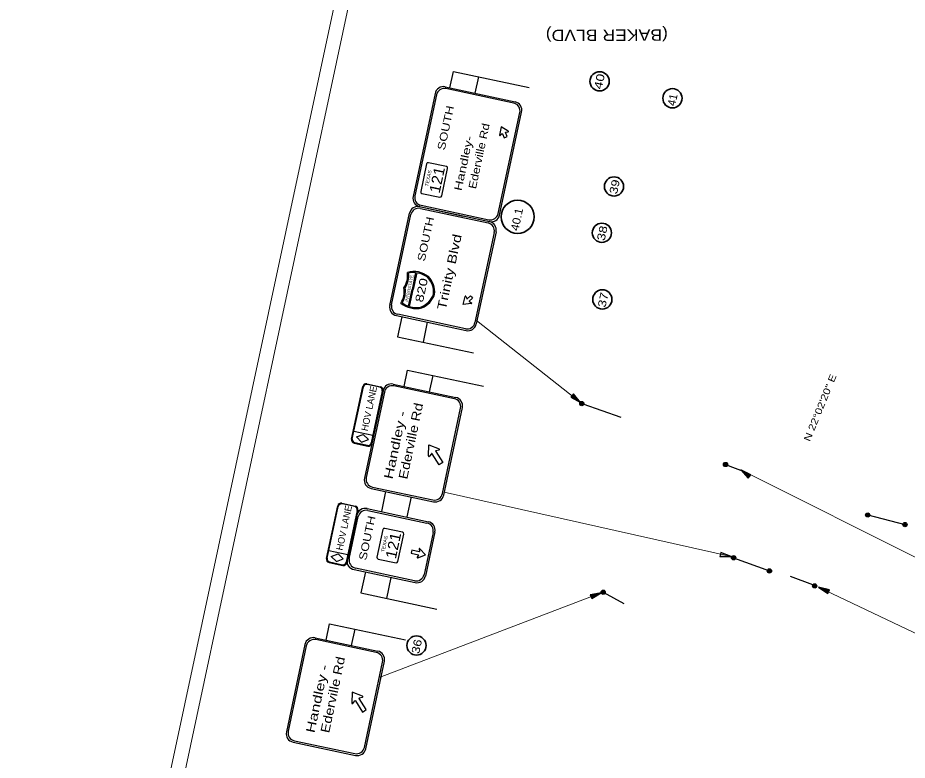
# Model space of a CAD drawing. Extents: x 2363411 to 2369702, y 6977197 to 6988655.
# Drawn here: x 2363411 to 2364967, y 6979218 to 6980518 of the extents above; entities that cross this region are included whole.
import ezdxf
from ezdxf.enums import TextEntityAlignment as Align

# ---------------------------------------------------------------- set-up
doc = ezdxf.new("R2010")
doc.units = 0
doc.header["$LTSCALE"] = 5.6
for name, color, linetype, lineweight in [('1', 7, 'Continuous', 25), ('10', 7, 'Continuous', 13), ('13', 7, 'Continuous', 13), ('17', 7, 'Continuous', 35), ('48', 7, 'Continuous', 25)]:
    doc.layers.add(name, color=color, linetype=linetype, lineweight=lineweight)
doc.layers.add('28', color=7, linetype='Continuous')

msp = doc.modelspace()

# ---------------------------------------------------------------- hatches: boundary and pattern name
at = {"layer": '1'}
for points in [[(2364395.849, 6979844.391), (2364383.344, 6979859.395), (2364378.757, 6979853.851)], [(2364400.643, 6979844.979, 1), (2364395.253, 6979839.817, 1)], [(2364652.119, 6979738.397, 1), (2364646.635, 6979733.335, 1)], [(2364675.941, 6979726.259), (2364689.19, 6979711.901), (2364693.5, 6979717.691)], [(2364900.421, 6979650.311, 1), (2364895.482, 6979644.716, 1)], [(2364965.668, 6979633.538, 1), (2364960.729, 6979627.943, 1)], [(2364659.135, 6979575), (2364640.906, 6979582.012), (2364639.602, 6979574.934)], [(2364665.911, 6979575.535, 1), (2364660.969, 6979569.942, 1)], [(2364728.487, 6979552.379, 1), (2364723.545, 6979546.786, 1)], [(2364438.384, 6979514.445, 1), (2364432.244, 6979510.203, 1)], [(2364807.983, 6979525.907, 1), (2364802.499, 6979520.845, 1)], [(2364811.897, 6979521.098), (2364828.08, 6979510.162), (2364830.948, 6979516.769)], [(2364432.027, 6979511.264), (2364412.779, 6979507.95), (2364415.284, 6979501.204)]]:
    msp.add_hatch(color=256, dxfattribs=at).paths.add_polyline_path(points)

# ---------------------------------------------------------------- linework, layer by layer
for p, q in [((2364167.135, 6980395.064), (2364173.274, 6980423.795)), ((2364173.274, 6980423.795), (2364305.856, 6980395.467)), ((2364211.638, 6980385.554), (2364217.777, 6980414.287)), ((2364159.115, 6980396.778), (2364281.159, 6980370.698)), ((2364281.102, 6980367.815), (2364160.369, 6980393.619)), ((2364141.265, 6980385.212), (2364102.765, 6980205.026)), ((2364143.627, 6980382.783), (2364105.906, 6980206.28)), ((2364251.811, 6980175.104), (2364289.567, 6980351.79)), ((2364254.104, 6980172.382), (2364292.597, 6980352.561)), ((2364255.297, 6980311.725), (2364258.277, 6980314.629)), ((2364264.669, 6980317.552), (2364268.795, 6980317.874)), ((2364269.112, 6980319.29), (2364269.086, 6980319.295)), ((2364161.015, 6980257.291), (2364129.782, 6980263.971)), ((2364126.447, 6980261.812), (2364116.153, 6980213.654)), ((2364152.886, 6980205.805), (2364163.181, 6980253.956)), ((2364118.319, 6980210.319), (2364149.551, 6980203.639)), ((2364114.33, 6980187.162), (2364236.725, 6980161.005)), ((2364114.33, 6980187.162), (2364191.247, 6980170.724)), ((2364116.766, 6980189.531), (2364235.118, 6980164.239)), ((2364062.029, 6980014.151), (2364096.539, 6980175.632)), ((2364065.17, 6980015.396), (2364098.9, 6980173.209)), ((2364115.583, 6980184.027), (2364233.929, 6980158.736)), ((2364244.748, 6980142.053), (2364211.027, 6979984.233)), ((2364247.883, 6980143.299), (2364213.379, 6979981.811)), ((2364107.307, 6980071.579), (2364101.041, 6980042.241)), ((2364109.199, 6980071.369), (2364102.89, 6980041.849)), ((2364094.775, 6980012.905), (2364101.041, 6980042.241)), ((2364096.583, 6980012.305), (2364102.89, 6980041.849)), ((2364195.117, 6980030.073), (2364196.649, 6980026.204)), ((2364197.436, 6980026.006), (2364197.448, 6980026.015)), ((2364201.289, 6980020.924), (2364204.923, 6980018.944)), ((2364194.344, 6979973.413), (2364075.983, 6979998.705)), ((2364073.575, 6979996.353), (2364195.589, 6979970.272)), ((2364083.219, 6979994.292), (2364075.789, 6979959.519)), ((2364127.721, 6979984.779), (2364120.293, 6979950.009)), ((2364075.789, 6979959.519), (2364208.371, 6979931.191)), ((2364087.14, 6979872.511), (2364093.279, 6979901.242)), ((2364093.279, 6979901.242), (2364225.861, 6979872.914)), ((2364131.643, 6979863.001), (2364137.782, 6979891.734)), ((2364068.045, 6979876.561), (2364177.43, 6979853.362)), ((2364175.005, 6979850.975), (2364069.311, 6979873.399)), ((2364050.211, 6979864.973), (2364017.718, 6979711.873)), ((2364052.569, 6979862.531), (2364020.85, 6979713.13)), ((2364154.184, 6979684.842), (2364185.895, 6979834.249)), ((2364156.54, 6979682.423), (2364189.035, 6979835.5)), ((2364399.628, 6979841.745), (2364466.091, 6979818.436)), ((2364129.725, 6979750.995), (2364130.48, 6979770.154)), ((2364130.48, 6979770.154), (2364148.254, 6979762.998)), ((2364134.884, 6979754.713), (2364131.548, 6979750.291)), ((2364148.547, 6979735.278), (2364136.006, 6979754.674)), ((2364148.151, 6979761.06), (2364142.742, 6979759.8)), ((2364649.381, 6979735.877), (2364688.003, 6979721.52)), ((2364029.292, 6979694.024), (2364138.684, 6979670.818)), ((2364031.74, 6979696.404), (2364137.434, 6979673.981)), ((2364054.763, 6979688.621), (2364047.333, 6979653.848)), ((2364099.265, 6979679.108), (2364091.837, 6979644.338)), ((2363989.737, 6979576.334), (2364006.381, 6979656.061)), ((2364022.274, 6979658.714), (2364129.853, 6979635.724)), ((2364023.528, 6979655.581), (2364127.058, 6979633.455)), ((2363991.052, 6979570.875), (2364006.844, 6979644.762)), ((2364897.949, 6979647.508), (2364963.203, 6979630.739)), ((2364049.852, 6979621.948), (2364039.558, 6979573.79)), ((2364084.42, 6979617.427), (2364053.187, 6979624.107)), ((2364076.291, 6979565.941), (2364086.586, 6979614.092)), ((2364137.876, 6979616.771), (2364122.157, 6979543.218)), ((2364141.011, 6979618.017), (2364124.448, 6979540.493)), ((2364113.435, 6979583.245), (2364113.424, 6979583.252)), ((2364113.528, 6979587.919), (2364114.043, 6979583.813)), ((2364041.724, 6979570.455), (2364072.956, 6979563.775)), ((2364112.468, 6979576.963), (2364110.222, 6979573.46)), ((2364663.442, 6979572.748), (2364726.016, 6979549.582)), ((2363999.523, 6979552.172), (2364106.722, 6979529.256)), ((2364105.476, 6979532.398), (2364001.93, 6979554.524)), ((2364019.498, 6979547.902), (2364011.642, 6979511.135)), ((2364064, 6979538.389), (2364056.146, 6979501.625)), ((2364762.642, 6979540.186), (2364801.264, 6979525.829)), ((2364011.642, 6979511.135), (2364144.224, 6979482.807)), ((2364435.318, 6979512.333), (2364471.648, 6979492.652)), ((2363950.653, 6979428.484), (2363956.792, 6979457.215)), ((2363956.792, 6979457.215), (2364089.374, 6979428.887)), ((2363995.156, 6979418.974), (2364001.295, 6979447.707)), ((2363931.558, 6979432.534), (2364040.943, 6979409.335)), ((2364038.518, 6979406.948), (2363932.824, 6979429.372)), ((2363913.724, 6979420.946), (2363881.231, 6979267.846)), ((2363916.082, 6979418.504), (2363884.363, 6979269.103)), ((2364020.053, 6979238.396), (2364052.548, 6979391.473)), ((2364017.697, 6979240.815), (2364049.408, 6979390.222)), ((2363997.515, 6979317.748), (2364000.851, 6979322.17)), ((2364001.973, 6979322.131), (2364014.514, 6979302.735)), ((2364020.861, 6979306.859), (2364008.311, 6979326.233)), ((2364008.709, 6979327.257), (2364014.118, 6979328.517)), ((2363895.253, 6979252.377), (2364000.947, 6979229.954)), ((2363892.805, 6979249.997), (2364002.197, 6979226.791))]:
    msp.add_line(p, q, dxfattribs=at)
at = {"layer": '1', "lineweight": 13}
for p, q in [((2364395.849, 6979844.391), (2364213.976, 6979987.64)), ((2364675.941, 6979726.259), (2365587.007, 6979269.736)), ((2364659.135, 6979575), (2364157.357, 6979687.495)), ((2364811.897, 6979521.098), (2365602.925, 6979144.273)), ((2364432.009, 6979511.012), (2364045.483, 6979363.861))]:
    msp.add_line(p, q, dxfattribs=at)
at = {"layer": '1'}
for points in [[(2364269.086, 6980319.295), (2364256.691, 6980326.558), (2364254.03, 6980312.435)], [(2364259.083, 6980314.476), (2364262.306, 6980307.386), (2364264.883, 6980308.563), (2364267.459, 6980309.748), (2364264.238, 6980316.823)], [(2364204.607, 6980017.529), (2364190.327, 6980015.966), (2364193.671, 6980029.943)], [(2364197.448, 6980026.015), (2364203.287, 6980031.169), (2364205.159, 6980029.041), (2364207.025, 6980026.907), (2364201.193, 6980021.767)], [(2364142.344, 6979758.776), (2364154.894, 6979739.402), (2364151.725, 6979737.342), (2364148.556, 6979735.284)], [(2364113.424, 6979583.252), (2364100.874, 6979586.105), (2364100.235, 6979583.341), (2364099.6, 6979580.58), (2364112.156, 6979577.721)], [(2364111.172, 6979572.36), (2364124.471, 6979577.813), (2364114.863, 6979588.489)], [(2364014.221, 6979330.455), (2363996.447, 6979337.611), (2363995.692, 6979318.452)], [(2364014.523, 6979302.741), (2364017.692, 6979304.799), (2364020.861, 6979306.859)]]:
    msp.add_lwpolyline(points, dxfattribs=at)
for points in [[(2364395.849, 6979844.391), (2364383.344, 6979859.395), (2364378.757, 6979853.851)], [(2364675.941, 6979726.259), (2364689.19, 6979711.901), (2364693.5, 6979717.691)], [(2364659.135, 6979575), (2364640.906, 6979582.012), (2364639.602, 6979574.934)], [(2364811.897, 6979521.098), (2364828.08, 6979510.162), (2364830.948, 6979516.769)], [(2364432.027, 6979511.264), (2364412.779, 6979507.95), (2364415.284, 6979501.204)]]:
    msp.add_lwpolyline(points, close=True, dxfattribs=at)
for centre in [(2364397.948, 6979842.398), (2364649.377, 6979735.866), (2364897.952, 6979647.513), (2364963.199, 6979630.741), (2364663.44, 6979572.739), (2364726.016, 6979549.582), (2364435.314, 6979512.324), (2364805.241, 6979523.376)]:
    msp.add_circle(centre, 3.732, dxfattribs=at)
for centre, radius, start, end in [((2364155.977, 6980382.065), 15.049, 77.93925, 169.35675), ((2364157.424, 6980379.833), 14.108, 77.93925, 167.93925), ((2364275.77, 6980354.738), 14.108, 347.93925, 68.3439), ((2364277.948, 6980356.005), 15.049, 346.76968, 76.63979), ((2364254.773, 6980312.274), 0.759, 169.23551, 314.61665), ((2364258.615, 6980314.28), 0.506, 24.49701, 134.48012), ((2364264.696, 6980317.051), 0.506, 94.51391, 204.49701), ((2364268.729, 6980318.634), 0.759, 274.37738, 59.75852), ((2364129.197, 6980261.219), 2.813, 77.93906, 167.93906), ((2364160.425, 6980254.547), 2.813, 347.93906, 77.93906), ((2364117.48, 6980201.884), 15.049, 167.93925, 257.93925), ((2364119.713, 6980203.331), 14.108, 167.93925, 257.93925), ((2364118.909, 6980213.066), 2.813, 167.93906, 257.93906), ((2364150.136, 6980206.394), 2.813, 257.93906, 347.93906), ((2364111.206, 6980172.499), 15.001, 77.94013, 167.94013), ((2364112.648, 6980170.273), 14.063, 77.94013, 167.94013), ((2364238.015, 6980178.052), 14.108, 257.93925, 347.93925), ((2364239.454, 6980175.826), 15.049, 257.93925, 346.76968), ((2364230.995, 6980144.989), 14.063, 347.94013, 77.94013), ((2364233.221, 6980146.431), 15.001, 347.94013, 77.94013), ((2364057.337, 6980065.842), 35.984, 325.11963, 9.96995), ((2364057.337, 6980065.842), 37.874, 326.31755, 7.31439), ((2364103.993, 6980031.645), 41.954, 51.80243, 105.50481), ((2364103.993, 6980031.645), 40.064, 85.24888, 103.11363), ((2364103.993, 6980031.645), 40.064, 52.01897, 82.53095), ((2364100.001, 6980037.044), 38.808, 355.77729, 42.42367), ((2364100.001, 6980037.044), 40.698, 355.41114, 42.64704), ((2364051.505, 6980038.547), 35.984, 325.90855, 10.75886), ((2364051.505, 6980038.547), 37.874, 328.56411, 9.56095), ((2364102.213, 6980047.395), 38.808, 293.45483, 340.10121), ((2364102.213, 6980047.395), 40.698, 293.23145, 340.46735), ((2364194.415, 6980029.786), 0.759, 21.26148, 166.64261), ((2364076.7, 6980011.015), 15.001, 167.94013, 257.94013), ((2364078.925, 6980012.457), 14.063, 167.94013, 257.94013), ((2364108.062, 6980050.691), 41.954, 230.37369, 284.07606), ((2364108.062, 6980050.691), 40.064, 232.76486, 250.62962), ((2364197.101, 6980026.386), 0.506, 201.398, 311.38111), ((2364201.519, 6980021.372), 0.506, 131.38111, 241.36421), ((2364204.553, 6980018.279), 0.759, 276.1196, 61.50074), ((2364108.062, 6980050.691), 40.064, 253.34754, 283.85953), ((2364197.273, 6979987.172), 14.063, 257.94013, 347.94013), ((2364198.715, 6979984.947), 15.001, 257.94013, 347.94013), ((2364064.927, 6979861.846), 15.049, 78.01448, 168.01448), ((2364066.376, 6979859.615), 14.108, 78.01448, 168.01447), ((2364172.091, 6979837.19), 14.108, 348.01448, 78.01448), ((2364174.322, 6979838.639), 15.049, 348.01447, 78.01447), ((2364130.74, 6979750.922), 1.012, 177.67774, 323.05888), ((2364135.414, 6979754.318), 0.675, 32.93925, 142.92235), ((2364142.892, 6979759.163), 0.675, 102.95614, 212.93925), ((2364147.902, 6979762.041), 1.012, 282.81961, 68.20075), ((2364032.426, 6979708.751), 15.049, 168.01448, 258.01448), ((2364034.657, 6979710.201), 14.108, 168.01447, 258.01447), ((2364140.371, 6979687.776), 14.108, 258.01447, 348.01447), ((2364141.821, 6979685.545), 15.049, 258.01447, 348.01447), ((2364019.149, 6979644.05), 15.001, 77.94013, 167.94013), ((2364020.591, 6979641.825), 14.063, 77.94013, 167.94013), ((2364124.122, 6979619.706), 14.063, 347.94013, 77.94013), ((2364126.348, 6979621.148), 15.001, 347.94013, 77.94013), ((2364052.602, 6979621.355), 2.813, 77.93906, 167.93906), ((2364083.829, 6979614.682), 2.813, 347.93906, 77.93906), ((2364112.058, 6979577.224), 0.506, 327.13184, 77.11494), ((2364113.548, 6979583.738), 0.506, 257.11494, 7.09805), ((2364114.287, 6979588.008), 0.759, 41.85344, 187.23458), ((2364004.873, 6979568.274), 14.063, 167.94013, 257.94013), ((2364042.313, 6979573.202), 2.813, 167.93906, 257.93906), ((2364073.541, 6979566.529), 2.813, 257.93906, 347.93906), ((2364110.867, 6979573.058), 0.759, 146.99531, 292.37645), ((2364108.404, 6979546.155), 14.063, 257.94013, 347.94013), ((2364109.846, 6979543.93), 15.001, 257.94013, 347.94013), ((2363928.44, 6979417.819), 15.049, 78.01448, 168.01448), ((2363929.889, 6979415.588), 14.108, 78.01448, 168.01447), ((2364035.604, 6979393.163), 14.108, 348.01448, 78.01448), ((2364037.834, 6979394.613), 15.049, 348.01447, 78.01447), ((2364013.868, 6979329.498), 1.012, 282.81961, 68.20075), ((2363996.707, 6979318.379), 1.012, 177.67774, 323.05888), ((2364001.38, 6979321.776), 0.675, 32.93925, 142.92235), ((2364008.858, 6979326.621), 0.675, 102.95614, 212.93925), ((2363895.939, 6979264.725), 15.049, 168.01448, 258.01448), ((2363898.17, 6979266.174), 14.108, 168.01447, 258.01447), ((2364003.884, 6979243.749), 14.108, 258.01447, 348.01447), ((2364005.334, 6979241.518), 15.049, 258.01447, 348.01447)]:
    msp.add_arc(centre, radius, start, end, dxfattribs=at)
msp.add_ellipse((2364002.685, 6979564.764), major_axis=(-15.18, 0), ratio=0.848877, start_param=6.07270093, end_param=7.64349725, dxfattribs=at)
at = {"layer": '10'}
for p, q in [((2363411.416, 6977949.748), (2365605.51, 6988218.434)), ((2363435.864, 6977944.524), (2365629.958, 6988213.21))]:
    msp.add_line(p, q, dxfattribs=at)
at = {"layer": '17'}
for centre, radius in [((2364429.066, 6980406.364), 16.828), ((2364556.437, 6980376.782), 16.828), ((2364454.242, 6980222.417), 16.828), ((2364285.71, 6980169.356), 29.053), ((2364433.042, 6980141.365), 16.828), ((2364433.849, 6980024.797), 16.828), ((2364108.769, 6979419.141), 16.828)]:
    msp.add_circle(centre, radius, dxfattribs=at)
at = {"layer": '48'}
for p, q in [((2364021.941, 6979877.055), (2364045.667, 6979871.986)), ((2364044.714, 6979871.06), (2364022.43, 6979875.821)), ((2363995.22, 6979780.272), (2364014.933, 6979872.515)), ((2363996.452, 6979780.764), (2364015.85, 6979871.561)), ((2364048.972, 6979864.482), (2364029.575, 6979773.685)), ((2363999.377, 6979794.453), (2364032.5, 6979787.375)), ((2364003.599, 6979784.054), (2364015.527, 6979788.554)), ((2364012.646, 6979775.071), (2364003.599, 6979784.054)), ((2364024.574, 6979779.572), (2364015.527, 6979788.554)), ((2363999.763, 6979773.258), (2364023.619, 6979768.16)), ((2364000.718, 6979774.187), (2364023.001, 6979769.424)), ((2364012.646, 6979775.071), (2364024.574, 6979779.572)), ((2363951.386, 6979571.358), (2363971.099, 6979663.601)), ((2363952.618, 6979571.85), (2363972.016, 6979662.647)), ((2363978.108, 6979668.142), (2364001.834, 6979663.072)), ((2364000.88, 6979662.146), (2363978.597, 6979666.907)), ((2364005.138, 6979655.568), (2363985.741, 6979564.771)), ((2364006.377, 6979656.062), (2363986.672, 6979563.817)), ((2363955.543, 6979585.539), (2363988.666, 6979578.461)), ((2363959.765, 6979575.14), (2363971.693, 6979579.64)), ((2363980.74, 6979570.658), (2363971.693, 6979579.64)), ((2363955.93, 6979564.344), (2363979.786, 6979559.246)), ((2363956.884, 6979565.273), (2363979.168, 6979560.51)), ((2363968.812, 6979566.157), (2363959.765, 6979575.14)), ((2363968.812, 6979566.157), (2363980.74, 6979570.658))]:
    msp.add_line(p, q, dxfattribs=at)
for centre, radius, start, end in [((2364020.709, 6979871.278), 5.909, 77.93633, 167.93633), ((2364021.277, 6979870.402), 5.54, 77.93633, 167.93633), ((2364043.555, 6979865.638), 5.54, 347.93633, 77.93633), ((2364044.432, 6979866.208), 5.909, 347.93633, 77.93633), ((2364000.998, 6979779.036), 5.909, 167.93575, 257.93575), ((2364001.875, 6979779.604), 5.54, 167.93575, 257.93575), ((2364024.159, 6979774.841), 5.54, 257.93575, 347.93575), ((2364024.728, 6979773.966), 5.909, 257.93575, 347.93575), ((2363976.876, 6979662.365), 5.909, 77.93633, 167.93633), ((2363977.444, 6979661.488), 5.54, 77.93633, 167.93633), ((2363999.722, 6979656.724), 5.54, 347.93633, 77.93633), ((2364000.599, 6979657.292), 5.909, 347.93633, 77.93633), ((2363957.164, 6979570.122), 5.909, 167.93575, 257.93575), ((2363958.041, 6979570.69), 5.54, 167.93575, 257.93575), ((2363980.326, 6979565.927), 5.54, 257.93575, 347.93575), ((2363980.894, 6979565.051), 5.909, 257.93575, 347.93575)]:
    msp.add_arc(centre, radius, start, end, dxfattribs=at)

# ---------------------------------------------------------------- texts
at = {"layer": '1'}
for s, height, rotation, width, p in [('SOUTH', 13.5, 77.94, 1.25, (2364166.371, 6980323.606)), ('Ederville Rd', 13.5, 77.94, 1.2, (2364224.84, 6980274.247)), ('Handley-', 13.5, 77.94, 1.35, (2364197.716, 6980261.638)), ('SOUTH', 13.5, 77.94, 1.25, (2364131.406, 6980129.121)), ('Trinity Blvd', 15.68, 77.939, 1.3, (2364173.999, 6980071.324)), ('Ederville Rd', 15.68, 78.014, 1.2, (2364106.531, 6979775.41)), ('Handley -', 15.68, 78.014, 1.35, (2364079.321, 6979768.47)), ('SOUTH', 13.5, 77.94, 1.25, (2364029.039, 6979605.905)), ('Ederville Rd', 15.68, 78.014, 1.2, (2363970.044, 6979331.384)), ('Handley -', 15.68, 78.014, 1.35, (2363942.834, 6979324.444))]:
    msp.add_text(s, height=height, rotation=rotation, dxfattribs=dict(at, width=width)).set_placement(p, align=Align.CENTER)
for s, height, width, p in [('TEXAS', 6, 1.1, (2364129.282, 6980221.934)), ('121', 18.75, 1.1, (2364149.179, 6980209.532)), ('INTERSTATE', 5.198, 1.1, (2364093.895, 6980020.375)), ('820', 14.18, 1.35, (2364119.965, 6980018.625)), ('TEXAS', 6, 1.1, (2364052.686, 6979582.069)), ('121', 18.75, 1.1, (2364072.583, 6979569.667))]:
    msp.add_text(s, height=height, rotation=77.939, dxfattribs=dict(at, width=width)).set_placement(p)
at = {"layer": '13', "width": 1.15}
msp.add_text('(BAKER BLVD)', height=20, rotation=180.198, dxfattribs=at).set_placement((2364548.481, 6980497.449))
at = {"layer": '17'}
for s, width, p in [('40', 1.3, (2364435.522, 6980404.769)), ('39', 1.2, (2364462.089, 6980220.584)), ('40.1', 1.1, (2364291.179, 6980163.366)), ('38', 1.25, (2364440.471, 6980139.261)), ('37', 1.25, (2364441.955, 6980022.491)), ('36', 1.2, (2364115.976, 6979416.006))]:
    msp.add_text(s, height=14, rotation=77.939, dxfattribs=dict(at, width=width)).set_placement(p, align=Align.CENTER)
msp.add_text('41', height=14, rotation=77.939, dxfattribs=at).set_placement((2364563.424, 6980372.612), align=Align.CENTER)
at = {"layer": '28', "width": 1.25}
msp.add_text('N 22°02\'20" E', height=12, rotation=67.836, dxfattribs=at).set_placement((2364820.275, 6979832.998), align=Align.CENTER)
at = {"layer": '48'}
for p in [(2364031.669, 6979832.678), (2363987.836, 6979623.763)]:
    msp.add_text('HOV LANE', height=11.82, rotation=77.935, dxfattribs=at).set_placement(p, align=Align.CENTER)

doc.saveas('drawing.dxf')
